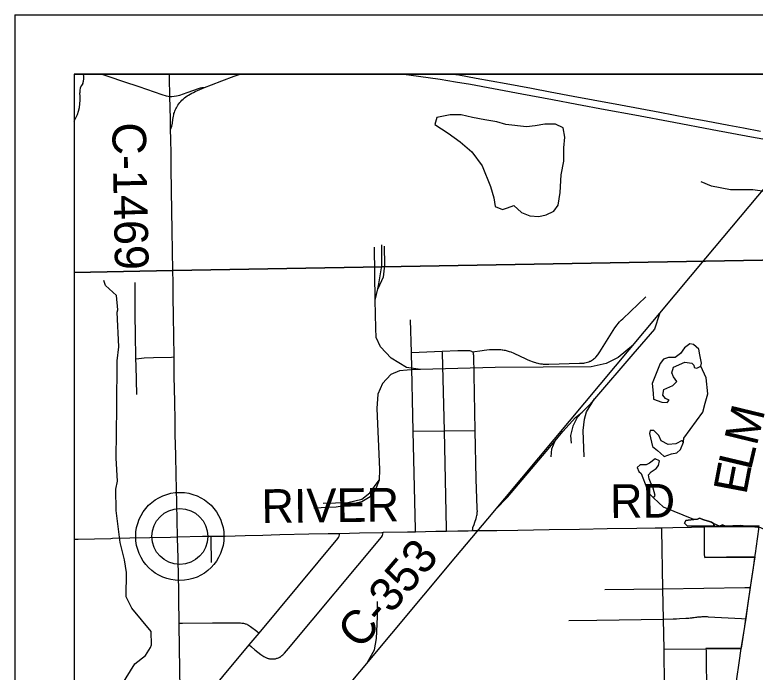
# Model space of a CAD drawing. Extents: x -6.4 to 34, y -4.2 to 22.
# Drawn here: x 2 to 3.249, y 19.89 to 21 of the extents above; entities that cross this region are included whole.
import ezdxf

# ---------------------------------------------------------------- set-up
doc = ezdxf.new("R2010")
doc.units = 0
for name, color, linetype in [('GM_X_Corporation', 7, 'Continuous'), ('GM_X_County_Road', 7, 'Continuous'), ('GM_X_County_Road_Text', 7, 'Continuous'), ('GM_X_Interchange_Ramps', 7, 'Continuous'), ('GM_X_Major_River_Text', 7, 'Continuous'), ('GM_X_Minor_Lake', 7, 'Continuous'), ('GM_X_Minor_River', 7, 'Continuous'), ('GM_X_Rail_Line', 7, 'Continuous'), ('GM_X_State_Route', 7, 'Continuous'), ('GM_X_Township_Road', 7, 'Continuous'), ('GM_X_Unincorporated', 7, 'Continuous'), ('GM_X_Unincorporated_Location', 7, 'Continuous'), ('SH_Data', 7, 'Continuous')]:
    doc.layers.add(name, color=color, linetype=linetype)

msp = doc.modelspace()

# ---------------------------------------------------------------- linework, layer by layer
at = {"layer": 'GM_X_Corporation'}
for points in [[(6.9491, 20.9), (2.1, 20.9), (2.1, 20.565), (2.2664, 20.5682), (3.3574, 20.5875), (3.4154, 20.5885), (3.6226, 20.5923), (3.724, 20.5933), (3.7296, 20.594), (3.7457, 20.5942), (3.7497, 20.5943), (5.4344, 20.629), (6.2003, 20.6471)], [(6.2003, 20.6471), (5.4344, 20.629), (3.7497, 20.5943), (3.7457, 20.5942), (3.7296, 20.594), (3.724, 20.5933), (3.6226, 20.5923), (3.4154, 20.5885), (3.3574, 20.5875), (2.2664, 20.5682), (2.1, 20.565), (2.1, 15.8155)], [(3.2557, 20.137), (3.2402, 20.1368), (3.2145, 20.1368), (3.1894, 20.1365), (3.163, 20.1359), (3.163, 20.1304), (3.1631, 20.1095), (3.1632, 20.0892), (3.1634, 20.0845), (3.2005, 20.0847), (3.2484, 20.0849), (3.2457, 20.0671), (3.2424, 20.045), (3.2408, 20.0339), (3.2367, 20.0069), (3.233, 19.9809), (3.2306, 19.9639), (3.2252, 19.9308), (3.166, 19.9302), (3.1662, 19.9257), (3.1666, 19.902), (3.1671, 19.8725)]]:
    msp.add_lwpolyline(points, dxfattribs=at)
at = {"layer": 'GM_X_County_Road'}
msp.add_line((2.2669, 20.5487), (2.2666, 20.5676), dxfattribs=at)
for points in [[(2.263, 20.7903), (2.2626, 20.8063), (2.2624, 20.8244), (2.2618, 20.8621), (2.2612, 20.8938), (2.2611, 20.9)], [(2.2666, 20.5676), (2.2656, 20.6354), (2.2646, 20.7032), (2.2639, 20.7411), (2.2635, 20.7653), (2.263, 20.7903)], [(2.2747, 20.1185), (2.2732, 20.175), (2.2727, 20.2003), (2.2723, 20.2226), (2.2715, 20.2565), (2.2707, 20.2913), (2.2704, 20.3143), (2.2699, 20.3472), (2.2691, 20.3895), (2.2687, 20.4223), (2.2682, 20.4585), (2.2678, 20.49), (2.2673, 20.5257), (2.2669, 20.5487)], [(2.4324, 20.1219), (2.4472, 20.1224), (2.4959, 20.1236), (2.5287, 20.1242), (2.5477, 20.1246), (2.5815, 20.1252), (2.619, 20.1262), (2.6216, 20.1263), (2.6623, 20.127), (2.6761, 20.1273), (2.6931, 20.1277), (2.7104, 20.1281), (2.7285, 20.1285), (2.7476, 20.1289), (2.7649, 20.1291), (2.7724, 20.1292), (2.7853, 20.1294), (2.8129, 20.1296), (2.8487, 20.1302), (2.9014, 20.1311), (2.9525, 20.1319), (2.9991, 20.1326), (3.0496, 20.1334), (3.0801, 20.1339), (3.0917, 20.1341), (3.1101, 20.1343), (3.1418, 20.135), (3.1632, 20.1353)], [(3.1632, 20.1353), (3.1896, 20.1359), (3.2147, 20.1362), (3.2404, 20.1362), (3.2559, 20.1364)], [(3.2486, 20.0844), (3.2495, 20.0907), (3.2532, 20.1155), (3.2558, 20.1355), (3.2559, 20.1364)], [(2.1648, 20.1162), (2.1938, 20.1168), (2.2278, 20.1174), (2.2628, 20.1182), (2.2747, 20.1185), (2.3166, 20.1196), (2.3312, 20.1198), (2.3551, 20.1201), (2.3888, 20.1207), (2.4187, 20.1215), (2.4324, 20.1219)], [(2.3956, 19.9363), (2.3992, 19.9332), (2.4052, 19.928), (2.4148, 19.9202), (2.4167, 19.9188), (2.4201, 19.9165), (2.4221, 19.9154), (2.4244, 19.9144), (2.4256, 19.9139), (2.4263, 19.9137), (2.4273, 19.9134), (2.4286, 19.9131), (2.4296, 19.9129), (2.4304, 19.9127), (2.4311, 19.9127), (2.4326, 19.9125), (2.4334, 19.9125), (2.4347, 19.9125), (2.4366, 19.9126), (2.4383, 19.9128), (2.4398, 19.913), (2.4421, 19.9136), (2.4434, 19.914), (2.445, 19.9146), (2.4459, 19.915), (2.4468, 19.9154), (2.4475, 19.9158), (2.4487, 19.9166), (2.4496, 19.9173), (2.4507, 19.9182), (2.4523, 19.9196), (2.4536, 19.9209), (2.4549, 19.9223), (2.4617, 19.9301), (2.6187, 20.1183), (2.6202, 20.1208), (2.6209, 20.1234), (2.6216, 20.1263)], [(2.1, 20.1148), (2.1067, 20.1149), (2.1618, 20.1161), (2.1648, 20.1162)], [(2.2844, 19.5722), (2.2844, 19.5732), (2.2839, 19.5916), (2.2835, 19.6084), (2.282, 19.6814), (2.2808, 19.7545), (2.2803, 19.7867), (2.2797, 19.8258), (2.2792, 19.8614), (2.2785, 19.8949), (2.2774, 19.9703), (2.2773, 19.9728), (2.2767, 20.0138), (2.2765, 20.0284), (2.276, 20.0517), (2.2754, 20.0818), (2.2751, 20.1011), (2.2747, 20.1154), (2.2747, 20.1185)], [(3.2254, 19.9302), (3.2308, 19.9633), (3.2332, 19.9803), (3.2369, 20.0064), (3.2409, 20.0333), (3.2426, 20.0444), (3.2459, 20.0666), (3.2486, 20.0844)], [(3.2014, 19.8073), (3.2041, 19.816), (3.2058, 19.8216), (3.2082, 19.8304), (3.2117, 19.8448), (3.2147, 19.8599), (3.2161, 19.8677), (3.2181, 19.8788), (3.2222, 19.9057), (3.2254, 19.9302)]]:
    msp.add_lwpolyline(points, dxfattribs=at)
at = {"layer": 'GM_X_Interchange_Ramps'}
for points in [[(2.1465, 20.9), (2.1467, 20.8999), (2.1589, 20.8961), (2.1836, 20.8875), (2.2094, 20.8787), (2.2482, 20.8653), (2.2555, 20.8633), (2.2587, 20.8624), (2.2618, 20.8621)], [(2.2626, 20.8063), (2.264, 20.8092), (2.2647, 20.812), (2.2659, 20.8171), (2.2667, 20.8232), (2.2676, 20.8289), (2.268, 20.831), (2.2685, 20.8331), (2.2692, 20.8353), (2.2699, 20.8374), (2.2706, 20.8392), (2.2714, 20.841), (2.2725, 20.8432), (2.2738, 20.8454), (2.275, 20.8474), (2.2765, 20.8496), (2.2782, 20.8519), (2.2799, 20.8539), (2.2818, 20.8559), (2.2839, 20.8578), (2.286, 20.8597), (2.2883, 20.8615), (2.2906, 20.8631), (2.293, 20.8646), (2.2959, 20.8662), (2.2985, 20.8677), (2.3015, 20.8691), (2.3044, 20.8706), (2.3124, 20.874), (2.3201, 20.877), (2.3316, 20.8816), (2.3494, 20.8887), (2.3698, 20.8964), (2.3802, 20.9)], [(2.2618, 20.8621), (2.2651, 20.862), (2.2687, 20.8624), (2.273, 20.8631), (2.2756, 20.8637), (2.2783, 20.8646), (2.2906, 20.8689), (2.3116, 20.8764), (2.3135, 20.8768), (2.3157, 20.8771), (2.3201, 20.877)]]:
    msp.add_lwpolyline(points, dxfattribs=at)
at = {"layer": 'GM_X_Major_River_Text'}
msp.add_lwpolyline([(2.1156, 20.9), (2.1, 20.9), (2.1, 20.8204)], dxfattribs=at)
for centre, radius, start, end in [((2.0892, 20.8933), 0.0273, 340.033, 14.1482), ((2.1293, 20.8704), 0.0198, 136.8065, 186.9296), ((2.0405, 20.8571), 0.0699, 328.3126, 8.9858)]:
    msp.add_arc(centre, radius, start, end, dxfattribs=at)
at = {"layer": 'GM_X_Minor_Lake'}
for points in [[(2.8281, 20.8149), (2.8129, 20.8195), (2.7932, 20.8226), (2.7719, 20.8267), (2.7529, 20.8313), (2.7344, 20.8313), (2.7118, 20.8264), (2.7086, 20.8149), (2.7311, 20.8002), (2.7514, 20.7854), (2.771, 20.7686), (2.7885, 20.7451), (2.8023, 20.71), (2.808, 20.6908), (2.8105, 20.6761), (2.8227, 20.6713), (2.831, 20.6742), (2.8419, 20.6778)], [(2.8281, 20.8149), (2.8129, 20.8195), (2.7932, 20.8226), (2.7719, 20.8267), (2.7529, 20.8313), (2.7344, 20.8313), (2.7118, 20.8264), (2.7086, 20.8149), (2.7311, 20.8002), (2.7514, 20.7854), (2.771, 20.7686), (2.7885, 20.7451), (2.8023, 20.71), (2.808, 20.6908), (2.8105, 20.6761), (2.8227, 20.6713), (2.831, 20.6742), (2.8419, 20.6778), (2.8549, 20.6663), (2.869, 20.6604), (2.8842, 20.6596), (2.8962, 20.6621), (2.9094, 20.6684), (2.9167, 20.6784), (2.9201, 20.7001), (2.9219, 20.7297), (2.9264, 20.7529), (2.926, 20.7753), (2.9279, 20.7936), (2.925, 20.8091), (2.9121, 20.8153), (2.8939, 20.8153), (2.8777, 20.8124), (2.8633, 20.8106), (2.8281, 20.8149)], [(2.8419, 20.6778), (2.8549, 20.6663), (2.869, 20.6604), (2.8842, 20.6596), (2.8962, 20.6621), (2.9094, 20.6684), (2.9167, 20.6784), (2.9201, 20.7001), (2.9219, 20.7297), (2.9264, 20.7529), (2.926, 20.7753), (2.9279, 20.7936), (2.925, 20.8091), (2.9121, 20.8153), (2.8939, 20.8153), (2.8777, 20.8124), (2.8633, 20.8106), (2.8281, 20.8149)], [(3.142, 20.4117), (3.1454, 20.4087), (3.1463, 20.4045), (3.1508, 20.4035), (3.1576, 20.407), (3.1583, 20.4116), (3.1557, 20.426), (3.1541, 20.4354), (3.1452, 20.4436), (3.1388, 20.4446), (3.1298, 20.438), (3.1232, 20.428), (3.1142, 20.4214), (3.1029, 20.4212), (3.0946, 20.4188), (3.0887, 20.4115), (3.0753, 20.3778)], [(3.0753, 20.3778), (3.0767, 20.3612), (3.0773, 20.3509), (3.0913, 20.3462), (3.1008, 20.3457), (3.1038, 20.3495), (3.0977, 20.3521), (3.093, 20.3577), (3.0951, 20.3672), (3.1101, 20.3743), (3.1168, 20.3812), (3.1114, 20.3887), (3.1082, 20.3955), (3.1111, 20.405), (3.1306, 20.4134), (3.142, 20.4117), (3.1454, 20.4087), (3.1463, 20.4045), (3.1508, 20.4035), (3.1576, 20.407), (3.1583, 20.4116), (3.1557, 20.426), (3.1541, 20.4354), (3.1452, 20.4436), (3.1388, 20.4446), (3.1298, 20.438), (3.1232, 20.428), (3.1142, 20.4214), (3.1029, 20.4212), (3.0946, 20.4188), (3.0887, 20.4115), (3.0753, 20.3778)], [(3.0753, 20.3778), (3.0767, 20.3612), (3.0773, 20.3509), (3.0913, 20.3462), (3.1008, 20.3457), (3.1038, 20.3495), (3.0977, 20.3521), (3.093, 20.3577), (3.0951, 20.3672), (3.1101, 20.3743), (3.1168, 20.3812), (3.1114, 20.3887), (3.1082, 20.3955), (3.1111, 20.405), (3.1306, 20.4134), (3.142, 20.4117)], [(3.1258, 20.2816), (3.1149, 20.2757), (3.1024, 20.2747), (3.0906, 20.281), (3.0863, 20.29), (3.0778, 20.2982), (3.0718, 20.2981), (3.0707, 20.2931), (3.0756, 20.2712)], [(3.0756, 20.2712), (3.0845, 20.2642), (3.0891, 20.2597), (3.0956, 20.2545), (3.1076, 20.2589), (3.1171, 20.2606), (3.123, 20.2664), (3.1281, 20.2783), (3.1258, 20.2816), (3.1149, 20.2757), (3.1024, 20.2747), (3.0906, 20.281), (3.0863, 20.29), (3.0778, 20.2982), (3.0718, 20.2981), (3.0707, 20.2931), (3.0756, 20.2712)], [(3.0756, 20.2712), (3.0845, 20.2642), (3.0891, 20.2597), (3.0956, 20.2545), (3.1076, 20.2589), (3.1171, 20.2606), (3.123, 20.2664), (3.1281, 20.2783), (3.1258, 20.2816)], [(3.0738, 20.2283), (3.082, 20.2342), (3.0857, 20.2392), (3.0874, 20.2472), (3.0802, 20.2501), (3.0705, 20.243), (3.0652, 20.2403), (3.055, 20.2405), (3.0498, 20.2358), (3.0526, 20.2291), (3.0568, 20.2257), (3.0663, 20.2009)], [(3.0663, 20.2009), (3.0679, 20.1952), (3.0706, 20.1911), (3.0759, 20.1861), (3.0775, 20.1847), (3.0805, 20.1882), (3.0769, 20.2007), (3.0725, 20.2112), (3.0702, 20.2165), (3.0693, 20.2233), (3.0738, 20.2283), (3.082, 20.2342), (3.0857, 20.2392), (3.0874, 20.2472), (3.0802, 20.2501), (3.0705, 20.243), (3.0652, 20.2403), (3.055, 20.2405), (3.0498, 20.2358), (3.0526, 20.2291), (3.0568, 20.2257), (3.0663, 20.2009)], [(3.0663, 20.2009), (3.0679, 20.1952), (3.0706, 20.1911), (3.0759, 20.1861), (3.0775, 20.1847), (3.0805, 20.1882), (3.0769, 20.2007), (3.0725, 20.2112), (3.0702, 20.2165), (3.0693, 20.2233), (3.0738, 20.2283)], [(3.1549, 20.1501), (3.1519, 20.1486), (3.1455, 20.1481), (3.1357, 20.1471), (3.1323, 20.1463), (3.1298, 20.1417), (3.1348, 20.1369)], [(3.1348, 20.1369), (3.1298, 20.1417), (3.1323, 20.1463), (3.1357, 20.1471), (3.1455, 20.1481), (3.1519, 20.1486), (3.1549, 20.1501), (3.1626, 20.1472), (3.1717, 20.1444), (3.1755, 20.1437), (3.1786, 20.1411), (3.1797, 20.1381), (3.1782, 20.1373), (3.1348, 20.1369)], [(3.1348, 20.1369), (3.1782, 20.1373), (3.1797, 20.1381), (3.1786, 20.1411), (3.1755, 20.1437), (3.1717, 20.1444), (3.1626, 20.1472), (3.1549, 20.1501)]]:
    msp.add_lwpolyline(points, dxfattribs=at)
at = {"layer": 'GM_X_Minor_River'}
for points in [[(3.3174, 20.6941), (3.245, 20.7046), (3.2075, 20.7046), (3.1753, 20.7109), (3.1581, 20.7178)], [(2.1807, 19.8687), (2.2024, 19.9041), (2.2203, 19.9184), (2.2291, 19.9319), (2.2305, 19.9365), (2.2301, 19.9588), (2.1973, 19.9981), (2.1879, 20.0176), (2.1883, 20.0582), (2.1849, 20.0798), (2.1775, 20.1092), (2.1709, 20.163), (2.1706, 20.199), (2.1734, 20.2127), (2.1712, 20.2514), (2.172, 20.3371), (2.1729, 20.4157), (2.1755, 20.4396), (2.1729, 20.498), (2.1736, 20.5018), (2.1717, 20.526), (2.1532, 20.5432), (2.15, 20.5514)], [(3.1281, 20.2783), (3.1287, 20.2851), (3.1605, 20.3293), (3.1644, 20.3446), (3.1694, 20.3602), (3.1666, 20.3871), (3.1576, 20.407)], [(3.1455, 20.1481), (3.0943, 20.169), (3.0775, 20.1847)], [(3.524, 20.1133), (3.4591, 20.103), (3.4354, 20.0965), (3.3948, 20.0851), (3.3494, 20.0866), (3.3278, 20.0869), (3.2953, 20.1068), (3.2787, 20.1243), (3.2585, 20.1338), (3.2236, 20.1381), (3.1987, 20.1369), (3.1941, 20.1387), (3.1888, 20.1367), (3.1786, 20.1411)]]:
    msp.add_lwpolyline(points, dxfattribs=at)
at = {"layer": 'GM_X_Rail_Line'}
for q in [(2.6069, 20.6077), (2.6123, 20.5375)]:
    msp.add_line((2.6081, 20.5185), q, dxfattribs=at)
for points in [[(2.1, 19.3146), (2.1225, 19.3415), (2.1651, 19.3926), (2.211, 19.4473), (2.2844, 19.5355), (2.3271, 19.5862), (2.407, 19.6818), (2.5079, 19.8027), (2.5818, 19.891), (2.744, 20.085), (2.7979, 20.1489), (2.8839, 20.252), (3.166, 20.5892), (3.4261, 20.9)], [(2.6123, 20.5375), (2.6141, 20.5456), (2.6194, 20.5761), (2.6191, 20.6116)], [(2.6233, 20.6095), (2.6239, 20.5773), (2.6213, 20.5569), (2.6123, 20.5375)], [(2.6844, 20.4012), (2.6606, 20.4044), (2.635, 20.4206), (2.6172, 20.4395), (2.6098, 20.4553), (2.6088, 20.4708), (2.6081, 20.5185)], [(3.0874, 20.4952), (3.0791, 20.469), (3.0424, 20.4272), (2.978, 20.3518)], [(3.0436, 20.4429), (3.0176, 20.4212), (2.9977, 20.4112), (2.9722, 20.4059), (2.8106, 20.4043), (2.6844, 20.4012)], [(2.6844, 20.4012), (2.6747, 20.401), (2.6488, 20.399), (2.6344, 20.3925), (2.6202, 20.3777), (2.6127, 20.3595), (2.6106, 20.3354), (2.6155, 20.2322), (2.6147, 20.2141)], [(2.978, 20.3518), (2.9704, 20.3429), (2.9572, 20.329)], [(2.9606, 20.2539), (2.959, 20.2983), (2.9609, 20.3176), (2.9644, 20.3295), (2.978, 20.3518)], [(2.9114, 20.2807), (2.9248, 20.2967), (2.9459, 20.3204), (2.9572, 20.329)], [(2.9572, 20.329), (2.9489, 20.3203), (2.9414, 20.3054), (2.9376, 20.2898), (2.9383, 20.2768)], [(2.8115, 20.1652), (2.8314, 20.1854), (2.8901, 20.2554), (2.9114, 20.2807)], [(2.9046, 20.2536), (2.906, 20.2671), (2.9114, 20.2807)], [(2.6147, 20.2141), (2.6083, 20.1988), (2.5997, 20.1864), (2.5853, 20.178), (2.5617, 20.1724), (2.5424, 20.169), (2.5042, 20.1672)], [(2.5204, 20.1753), (2.5619, 20.1768), (2.5852, 20.1824), (2.5992, 20.1927), (2.6147, 20.2141)], [(2.5942, 19.9058), (2.6066, 19.9277), (2.6103, 19.9472), (2.6117, 19.9839), (2.6116, 20.0095)]]:
    msp.add_lwpolyline(points, dxfattribs=at)
at = {"layer": 'GM_X_State_Route'}
for points in [[(2.6564, 20.9), (2.681, 20.8966), (2.7175, 20.8913), (2.7436, 20.887), (2.7688, 20.8827), (2.8552, 20.8665), (2.9069, 20.8569), (2.948, 20.8492), (2.9961, 20.8402), (3.0462, 20.831), (3.1116, 20.8187), (3.1764, 20.8066), (3.243, 20.7942), (3.287, 20.786), (3.3279, 20.7782), (3.3466, 20.7748)], [(2.7391, 20.9), (2.7491, 20.8984), (2.7782, 20.8933), (2.8289, 20.8838), (2.8718, 20.8759), (2.9029, 20.8701), (2.942, 20.8629), (2.9756, 20.8565), (3.0217, 20.8479), (3.0881, 20.8356), (3.1345, 20.8268), (3.1663, 20.8208), (3.2045, 20.8137), (3.2293, 20.8092), (3.258, 20.8036)]]:
    msp.add_lwpolyline(points, dxfattribs=at)
at = {"layer": 'GM_X_Township_Road'}
for p, q in [((3.0953, 19.929), (3.1662, 19.9297)), ((3.1662, 19.9297), (3.2254, 19.9302))]:
    msp.add_line(p, q, dxfattribs=at)
for points in [[(2.2056, 20.359), (2.2046, 20.4074), (2.2043, 20.4191), (2.2037, 20.462), (2.2032, 20.4918), (2.2029, 20.5483)], [(2.7724, 20.431), (2.7887, 20.4335), (2.792, 20.4339), (2.7963, 20.4344), (2.8007, 20.4347), (2.804, 20.435), (2.8072, 20.4351), (2.8127, 20.4351), (2.8155, 20.435), (2.8179, 20.4349), (2.8199, 20.4347), (2.8223, 20.4344), (2.8234, 20.4343), (2.8257, 20.4339), (2.8274, 20.4336), (2.829, 20.4332), (2.8322, 20.4324), (2.834, 20.4318), (2.8366, 20.4308), (2.8417, 20.4287), (2.8454, 20.4271), (2.8494, 20.4253), (2.8643, 20.4183), (2.8684, 20.4165), (2.8743, 20.4141), (2.8764, 20.4134), (2.8782, 20.4128), (2.8798, 20.4123), (2.8826, 20.4117), (2.8839, 20.4114), (2.8868, 20.4109), (2.8879, 20.4108), (2.8894, 20.4106), (2.8914, 20.4104), (2.8942, 20.4103), (2.8972, 20.4103), (2.9009, 20.4103), (2.9528, 20.4116), (2.9575, 20.4118), (2.9602, 20.4121), (2.9618, 20.4124), (2.964, 20.4129), (2.9663, 20.4136), (2.9683, 20.4142), (2.9702, 20.4151), (2.9713, 20.4155), (2.973, 20.4164), (2.9747, 20.4175), (2.976, 20.4185), (2.9775, 20.4196), (2.9788, 20.4207), (2.98, 20.4219), (2.9835, 20.4261), (2.9869, 20.4308), (3.0125, 20.4713), (3.016, 20.4764), (3.0178, 20.4787), (3.0203, 20.4815), (3.0227, 20.4842), (3.0255, 20.487), (3.0645, 20.5236)], [(2.6761, 20.1273), (2.676, 20.1312), (2.6721, 20.2969), (2.669, 20.4301), (2.6678, 20.4853)], [(2.2043, 20.4191), (2.2094, 20.42), (2.2183, 20.4208), (2.2338, 20.4213), (2.2645, 20.4222), (2.2687, 20.4223)], [(2.669, 20.4301), (2.7212, 20.4322), (2.7473, 20.4332), (2.7501, 20.4333), (2.765, 20.4332), (2.7673, 20.433), (2.7686, 20.4328), (2.7704, 20.4322), (2.7712, 20.4318), (2.7724, 20.431)], [(2.7285, 20.1285), (2.7284, 20.132), (2.7247, 20.2975), (2.7213, 20.4295), (2.7212, 20.4322)], [(2.7724, 20.1292), (2.7726, 20.1322), (2.7729, 20.1342), (2.7748, 20.1396), (2.776, 20.1432), (2.7767, 20.1453), (2.7777, 20.1481), (2.7783, 20.1499), (2.7789, 20.1523), (2.7794, 20.1545), (2.7798, 20.1563), (2.78, 20.1577), (2.7801, 20.159), (2.7802, 20.1605), (2.7803, 20.1623), (2.7802, 20.1648), (2.7801, 20.1672), (2.7785, 20.2163), (2.7765, 20.2984), (2.7741, 20.4245), (2.7741, 20.4253), (2.774, 20.426), (2.774, 20.4272), (2.7739, 20.4279), (2.7737, 20.4289), (2.7731, 20.4301), (2.7724, 20.431)], [(2.6721, 20.2969), (2.7247, 20.2975), (2.7765, 20.2984)], [(2.2797, 19.8258), (2.2894, 19.8257), (2.298, 19.8259), (2.3, 19.826), (2.3015, 19.8262), (2.3027, 19.8265), (2.3038, 19.8269), (2.3044, 19.8272), (2.305, 19.8276), (2.3059, 19.8284), (2.3066, 19.8292), (2.3956, 19.9363), (2.4122, 19.9563), (2.5448, 20.1159), (2.5462, 20.1176), (2.5469, 20.1187), (2.5474, 20.1201), (2.5476, 20.1223), (2.5477, 20.1246)], [(3.0974, 19.7808), (3.0962, 19.8661), (3.0953, 19.929), (3.0944, 19.9798), (3.0935, 20.0309), (3.0917, 20.1308), (3.0917, 20.1341)], [(2.3317, 20.0756), (2.3312, 20.1151), (2.3312, 20.1198)], [(3.1636, 20.084), (3.2007, 20.0842), (3.2486, 20.0844)], [(2.9954, 20.0297), (3.0935, 20.0309), (3.2314, 20.0332), (3.2409, 20.0333)], [(2.2773, 19.9728), (2.2831, 19.9729), (2.3335, 19.9733)], [(2.3335, 19.9733), (2.3775, 19.9735), (2.3786, 19.9735), (2.3795, 19.9735), (2.3806, 19.9734), (2.3829, 19.9732), (2.3836, 19.9731), (2.3844, 19.973), (2.3858, 19.9727), (2.3873, 19.9724), (2.3885, 19.972), (2.3897, 19.9716), (2.3913, 19.971), (2.392, 19.9707), (2.3933, 19.97), (2.3945, 19.9693), (2.3961, 19.9683), (2.3977, 19.9672), (2.4083, 19.9592), (2.4122, 19.9563)], [(2.9347, 19.9775), (2.982, 19.9782), (3.0944, 19.9798), (3.1107, 19.9802), (3.1165, 19.9804), (3.1213, 19.9806), (3.1318, 19.9812), (3.1342, 19.9813), (3.1371, 19.9815), (3.1392, 19.9817), (3.1403, 19.9819), (3.1411, 19.982), (3.1425, 19.9821), (3.1439, 19.9823), (3.1461, 19.9826), (3.1481, 19.9829), (3.1503, 19.9832), (3.1522, 19.9834), (3.1537, 19.9836), (3.1558, 19.9838), (3.1577, 19.9839), (3.1596, 19.9841), (3.161, 19.9841), (3.1623, 19.9842), (3.1633, 19.9841), (3.1652, 19.9841), (3.1667, 19.984), (3.168, 19.984), (3.1695, 19.9839), (3.2261, 19.9807), (3.2332, 19.9803)]]:
    msp.add_lwpolyline(points, dxfattribs=at)
at = {"layer": 'GM_X_Unincorporated'}
for radius in [0.0744, 0.0472]:
    msp.add_circle((2.2784, 20.1193), radius, dxfattribs=at)
at = {"layer": 'GM_X_Unincorporated_Location'}
msp.add_line((2.2784, 20.1193), (2.2784, 20.1193), dxfattribs=at)
at = {"layer": 'SH_Data'}
for p, q in [((2, 21), (9, 21)), ((2, 21), (2, 14)), ((2.1, 20.9), (2.1, 14.1)), ((2.1, 20.9), (8.9, 20.9))]:
    msp.add_line(p, q, dxfattribs=at)

# ---------------------------------------------------------------- texts
at = {"layer": 'GM_X_County_Road_Text'}
for s, height, rotation, p in [('C-1469', 0.05682, 271.1416, (2.1642, 20.8178)), ('M', 0.0568, 76.3527, (3.2515, 20.2708)), ('L', 0.0568, 76.6763, (3.2418, 20.2296)), ('E', 0.0568, 79.2183, (3.2339, 20.1885)), ('RIVER', 0.05682, 0.6529, (2.4164, 20.1421)), ('RD', 0.05682, 0.4937, (3.0044, 20.1505)), ('C-353', 0.05682, 49.4889, (2.583, 19.9265))]:
    msp.add_text(s, height=height, rotation=rotation, dxfattribs=at).set_placement(p)

doc.saveas('drawing.dxf')
